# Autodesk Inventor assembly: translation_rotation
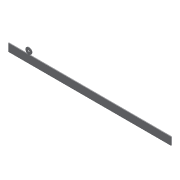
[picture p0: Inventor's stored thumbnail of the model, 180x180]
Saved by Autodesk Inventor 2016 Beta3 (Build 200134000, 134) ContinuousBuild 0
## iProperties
Created: 2016-03
Part Number: translation_rotation
Document SubType Name: Assembly
Designer: Gaurav
Author: Gaurav
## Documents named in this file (3)
- D:\My Data\Books_Final Books\Autodesk Inventor 2015_resources\Chapter 7\Wheel_motion\translation_rotation.iam
- D:\My Data\Books_Final Books\Autodesk Inventor 2015_resources\Chapter 7\Wheel_motion\base_wall.ipt
- D:\My Data\Books_Final Books\Autodesk Inventor 2015_resources\Chapter 7\Wheel_motion\wheel.ipt
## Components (2 placed, 2 different names)
1. base_wall:1 — Mate:1, Flush:1, Tangent:1, Mate:2, Mate:3, Rotation/Translation:1
2. wheel:1 — Flush:1, Tangent:1, Mate:4, Rotation/Translation:1
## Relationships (7: Mate 4, Flush 1, Tangent 1, RelateRotateTranslate 1)
- Mate:1: base_wall:1
- Flush:1: base_wall:1 ↔ wheel:1
- Tangent:1: base_wall:1 ↔ wheel:1
- Mate:2: base_wall:1
- Mate:3: base_wall:1
- Mate:4: wheel:1
- Rotation/Translation:1 [RelateRotateTranslate]: base_wall:1 ↔ wheel:1
